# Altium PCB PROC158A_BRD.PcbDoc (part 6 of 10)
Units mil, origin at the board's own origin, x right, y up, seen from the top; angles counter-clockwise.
Board outline 3346.45 x 4921.26 mil, 8 copper layers (Top Layer, GND1, SIG1, PWR1, PWR2, SIG2, GND2, Bottom Layer), stack 54.534 mil thick; 718 components, 459 nets, 2307 pads, 1179 vias.
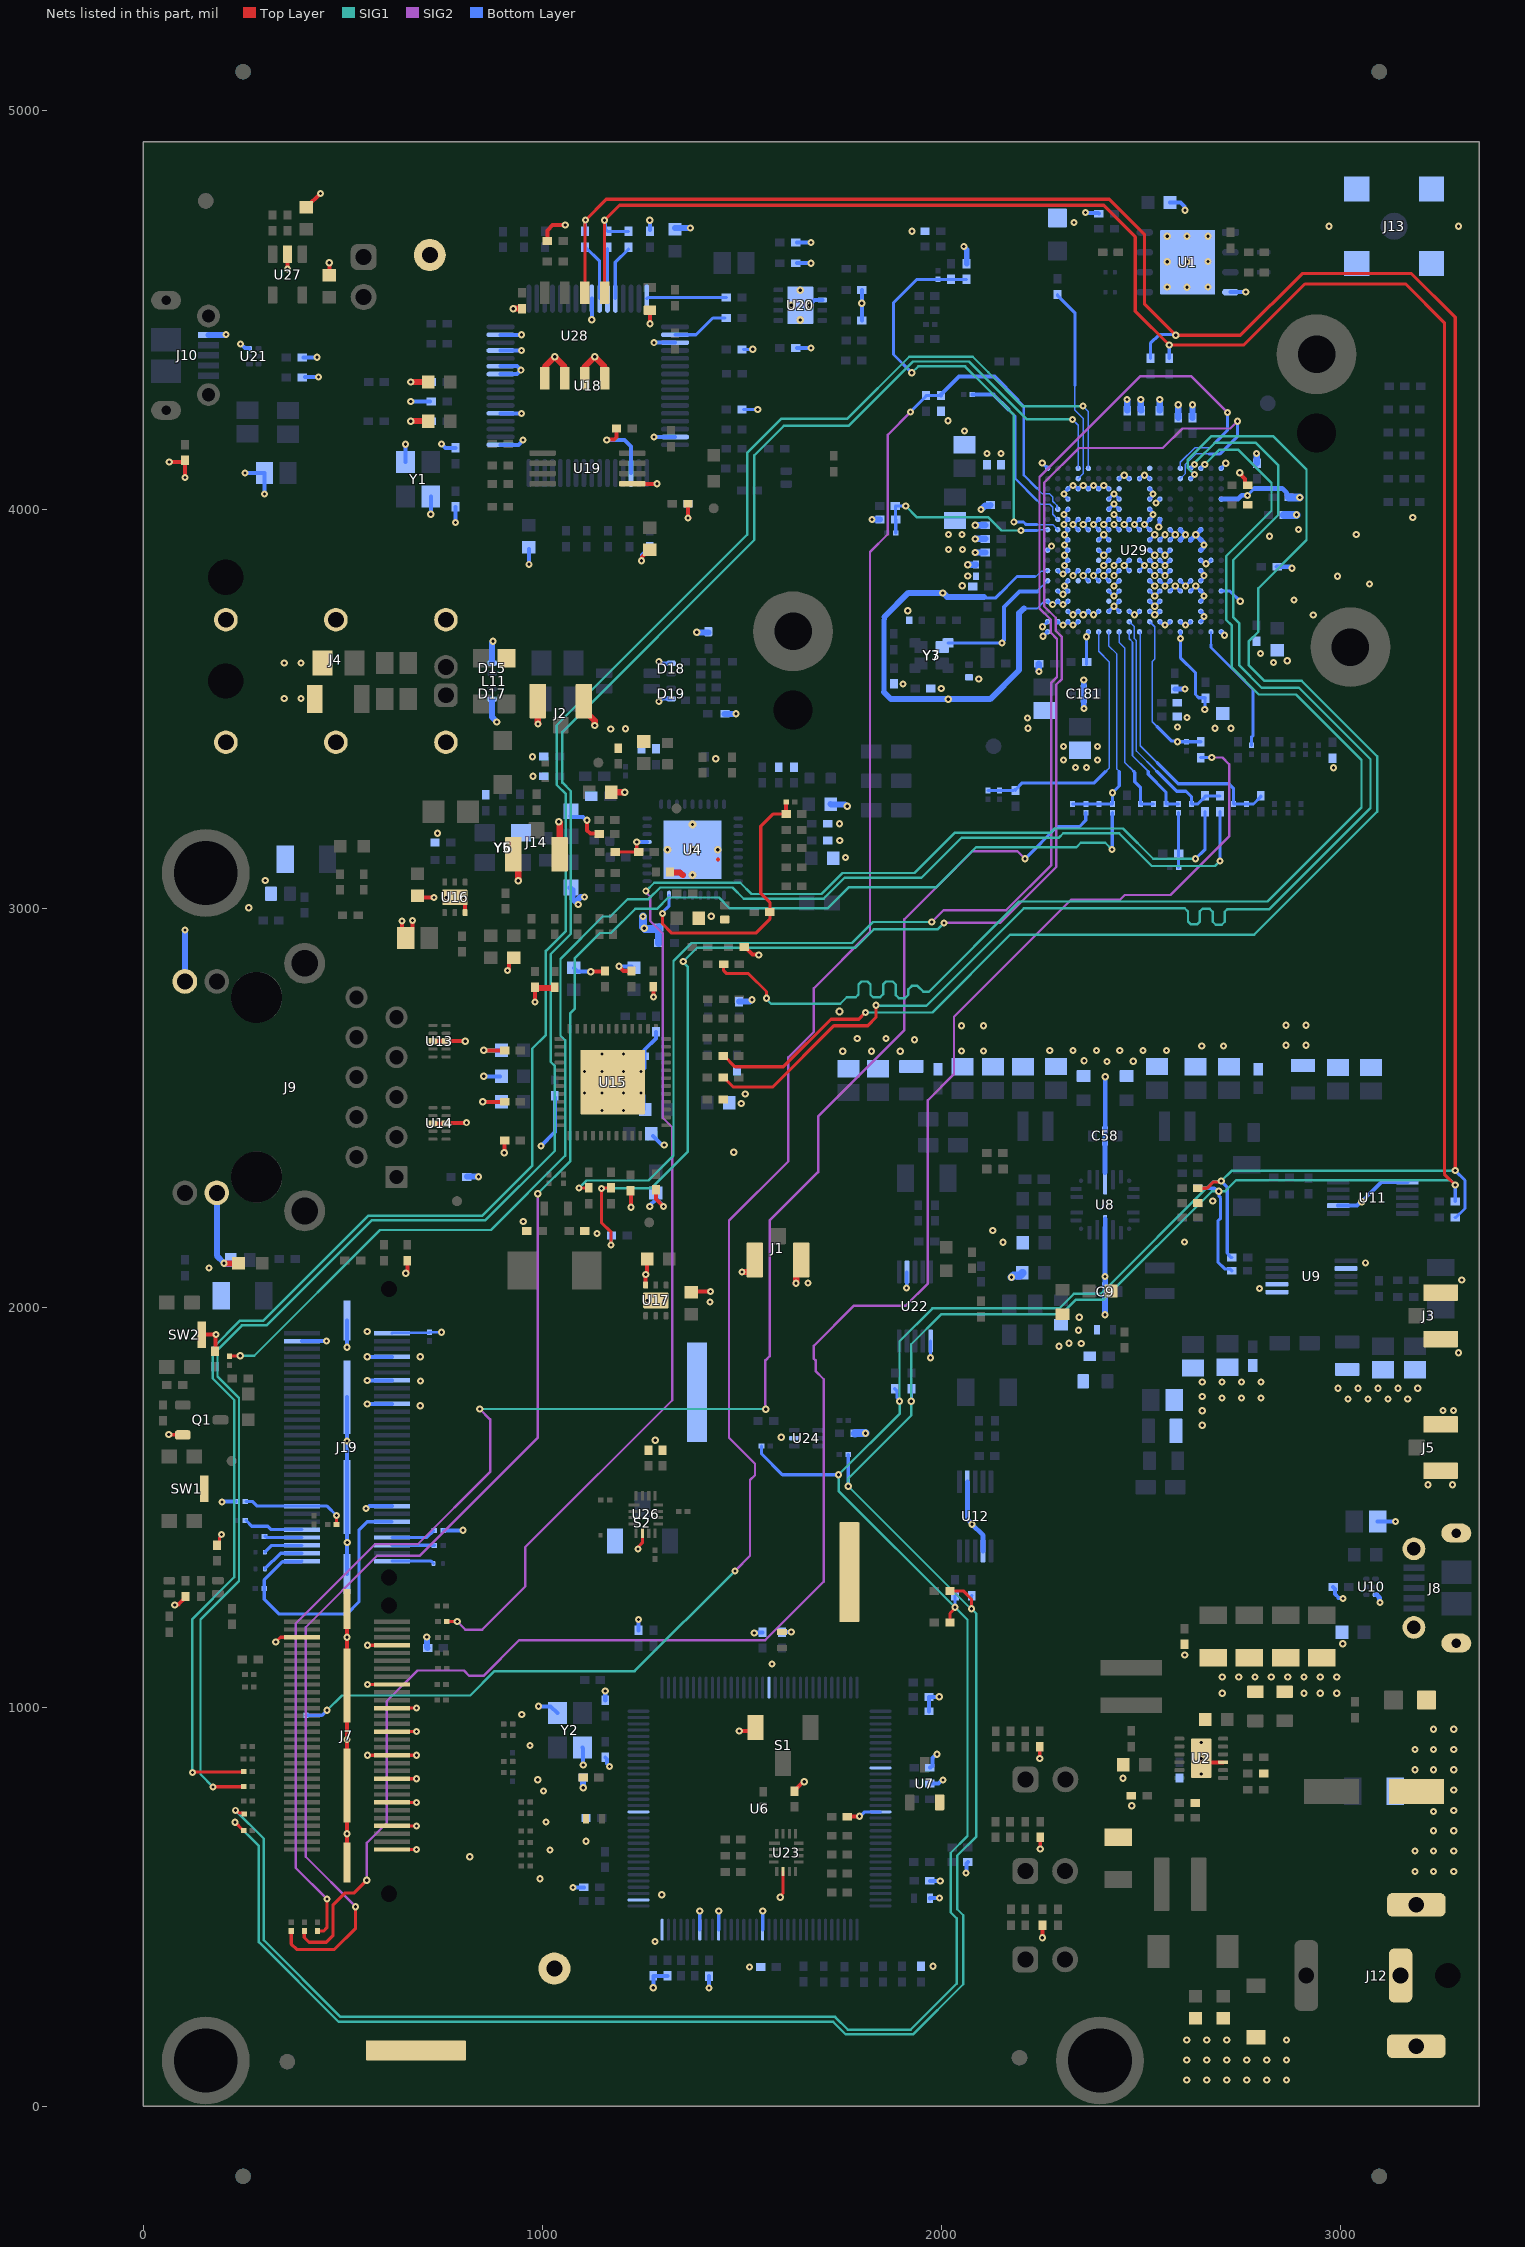
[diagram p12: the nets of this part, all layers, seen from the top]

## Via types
v1: diameter 18, hole 8, Top Layer to Bottom Layer, tented both sides, 1112 vias
v2: diameter 19.68, hole 7.87, Top Layer to Bottom Layer, 28 vias
v3: diameter 20, hole 10, Top Layer to Bottom Layer, tented both sides, 26 vias
v4: diameter 16/18/18/18/18/18/18/16 (per signal layer), hole 8, Top Layer to Bottom Layer, tented both sides, 13 vias

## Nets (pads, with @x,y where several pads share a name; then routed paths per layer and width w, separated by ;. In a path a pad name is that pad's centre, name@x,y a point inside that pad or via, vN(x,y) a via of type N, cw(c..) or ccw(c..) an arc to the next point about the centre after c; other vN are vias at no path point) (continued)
GND: C1.1 C2.1 C4.2 C5.1 C6.1 C7.2 C8.1 C9.2 C10.2 C11.1 C12.1 C13.1 C15.2 C16.2 C18.1 C20.2 C22.1 C23.2 C24.1 C25.2 C26.2 C27.1 C28.1 C29.2 C30.2 C31.2 C32.1 C33.2 C35.1 C36.1 C37.2 C38.2 C39.2 C40.2 C41.2 C42.1 C43.1 C44.2 C45.2 C46.1 C47.1 C48.2 C49.2 C50.2 C51.1 C52.2 C53.2 C54.1 C55.1 C56.2 C57.2 C58.2 C59.2 C60.2 C61.2 C62.2 C63.1 C64.1 C65.2 C66.1 C67.1 C68.2 C69.1 C70.2 C71.1 C72.2 C73.1 C74.1 C75.1 C76.1 C77.2 C78.2 C79.2 C80.1 C82.2 C83.2 C84.2 C85.2 C86.2 C87.2 C88.2 C89.2 C90.2 C91.2 C92.1 C93.2 C94.2 C95.2 C96.1 C97.2 C98.1 C99.2 C100.2 C101.2 C102.2 C103.2 C104.2 C105.1 C106.2 C107.1 C108.2 C109.1 C110.2 C111.1 C112.2 C113.1 C114.2 C115.1 C116.2 C117.1 C118.1 C119.2 C120.2 C121.2 C122.2 C124.2 C125.2 C126.2 C127.2 C128.2 C129.2 C130.2 C131.1 C132.2 C133.2 C134.2 C135.1 C136.1 C137.1 C138.1 C139.1 C140.1 C141.1 C142.1 C143.2 C144.1 C145.2 C146.1 C147.1 C148.1 C149.1 C150.1 C151.2 C152.2 C153.1 C154.2 C155.1 C158.2 C159.2 C160.2 C163.1 C164.1 C165.1 C166.2 C167.2 C168.1 C169.2 C170.1 C171.1 C172.1 C173.1 C174.1 C175.1 C176.1 C177.1 C178.1 C180.2 C181.2 C182.2 C183.2 C184.2 C185.2 C186.2 C187.2 C188.2 C189.2 C190.2 C191.2 C192.2 C193.2 C194.2 C195.2 C198.2 C199.2 C200.1 D1.2 D3.1 D6.2 D8.2 D10.1 D12.2 D14.1 D15.2 D17.2 D18.2 D19.2 J1.2 J1.3 J2.2 J2.3 J3.2 J3.3 J4.S1 J4.S2 J4.S3 J4.S4 J4.S5 J4.S6 J5.2 J5.3 J7.5 J7.8 J7.18 J7.24 J7.30 J7.36 J7.42 J7.48 J7.54 J7.60 J7.MP1 J7.MP2 J7.MP3 J7.MP4 J8.6 J8.9 J8.10 J8.11 J9.12 J9.13 J10.5 J12.2 J12.S1 J12.S2 J13.2 J14.2 J14.3 J19.16 J19.42 J19.48 J19.54 J19.57 J19.60 J19.MP1 J19.MP2 J19.MP3 J19.MP4 J21.1 J22.1 J23.1 L11.3 NT1.1 NT2.2 NT3.2 NT4.2 Q1.2 R1.2 R2.1 R8.2 R10.1 R17.1 R76.1 R86.1 R97.1 R102.2 R118.1 R119.2 R123.2 R126.2 R130.2 R137.1 R142.1 R143.1 R157.1 R172.1 R174.1 R175.1 R185.2 R194.1 R196.2 R203.2 R204.1 R208.1 R209.1 R251.2 R267.1 R282.1 R283.2 R285.1 R287.1 R288.1 R289.1 R294.1 R296.2 R302.1 R303.1 R307.1 R312.1 R313.1 R321.1 R326.1 R335.1 R337.2 R350.2 R400.2 R417.1 R512.2 S1.3 S2.3 SW1.5 SW2.5 TP7.1 TP9.1 U1.4 U1.9 U2.9 U2.13 U4.37 U6.10 U6.17 U6.48 U6.55 U6.58 U6.64 U6.66 U6.80 U6.114 U7.2 U8.10 U8.22 U9.1 U9.2 U9.7 U10.3 U11.1 U11.7 U12.2 U12.7 U13.3@725.63,2668.11 U13.8@758.51,2668.11 U14.3@725.63,2462.03 U14.8@758.51,2462.03 U15.49@1175.93,2565.54 U16.3 U16.7@780.58,3028.35 U17.3 U17.7@1283.94,2018.66 U18.1 U18.5 U18.10 U18.11 U18.13 U18.15 U18.25 U18.35 U18.47 U18.51 U19.5 U20.6 U20.9@1645.9,4511.81 U21.3 U22.1 U22.7 U23.6 U24.2 U26.6 U27.2 U28.1 U28.2 U28.3 U28.4 U29.A1 U29.A5 U29.A14 U29.A18 U29.B1 U29.B2 U29.B3 U29.B4 U29.B12 U29.B13 U29.B14 U29.B15 U29.B16 U29.C3 U29.C4 U29.C5 U29.C6 U29.C7 U29.C8 U29.C9 U29.C10 U29.C11 U29.C12 U29.C16 U29.D1 U29.D2 U29.D3 U29.D7 U29.D8 U29.D11 U29.D12 U29.D16 U29.E2 U29.E3 U29.E7 U29.E8 U29.E11 U29.E12 U29.E13 U29.E14 U29.E15 U29.E16 U29.E18 U29.F1 U29.F3 U29.F4 U29.F5 U29.F6 U29.F7 U29.F8 U29.F11 U29.F12 U29.F13 U29.F14 U29.F15 U29.F16 U29.G1 U29.G2 U29.G3 U29.G4 U29.G5 U29.G6 U29.G7 U29.G8 U29.G9 U29.G10 U29.G11 U29.G12 U29.G13 U29.G16 U29.H3 U29.H6 U29.H7 U29.H8 U29.H9 U29.H10 U29.H11 U29.H12 U29.H13 U29.H16 U29.H17 U29.J1 U29.J3 U29.J6 U29.J7 U29.J11 U29.J12 U29.J13 U29.J16 U29.K3 U29.K6 U29.K7 U29.K11 U29.K12 U29.K13 U29.K14 U29.K15 U29.K16 U29.L3 U29.L4 U29.L5 U29.L6 U29.L7 U29.L8 U29.L9 U29.L10 U29.L11 U29.L13 U29.L14 U29.L16 U29.M3 U29.M4 U29.M5 U29.M6 U29.M7 U29.M8 U29.M9 U29.M10 U29.M11 U29.M12 U29.N3 U29.N7 U29.N8 U29.N11 U29.P3 U29.P7 U29.P8 U29.P11 U29.P12 U29.P18 U29.R3 U29.R4 U29.R5 U29.R6 U29.R7 U29.R8 U29.R11 U29.T8 U29.T9 U29.T10 U29.T11 U29.U1 U29.U11 U29.U18 Y1.2 Y1.4 Y2.2 Y2.4 Y3.2 Y5.2 Y6.2 Y7.2 | length 15864.1
  Top Layer w7: v1(1595.75,523.58) 1595.75,526.56 1602.75,533.56 U23.6@1602.75,587.94
  Top Layer w8: R267.1@185.16,1405.66 191,1411.5 191,1423.93 196.31,1429.24 v1(196.31,1431.94) ; v1(332.09,1163.08) 343.68,1174.67 J7.5@397.49,1174.67 ; v1@561.77,879.4 v1@684.4,879.4 ; v1@561.77,1056.56 J7.18@623.08,1056.56 ; v1@561.77,1154.99 J7.8@623.08,1154.99 ; J7.60@623.08,643.18 v1@684.4,643.18 ; J7.54@623.08,702.23 v1@684.4,702.23 ; J7.48@623.08,761.29 v1@684.4,761.29 ; J7.42@623.08,820.34 v1@684.4,820.34 ; J7.30@623.08,938.45 v1@684.4,938.45 ; J7.24@623.08,997.51 v1@684.4,997.51 ; v1(1239,1395.81) 1240.91,1397.72 1240.91,1402.2 1250.43,1411.72 U26.6@1250.43,1435.19 ; v1(2245.64,871.29) R313.1@2245.64,900.17 ; v1(2246.93,644.67) R307.1@2246.93,673.54
  Top Layer w10: v1(63.77,1682.53) 64.12,1682.18 98.66,1682.18 Q1.2@99.01,1681.83 ; v1(64.94,4119.21) 104.25,4119.21 v1(104.25,4079.9) ; v1(79,1256) 80.53,1257.53 88.5,1257.53 105.96,1274.99 C105.1@105.96,1276.96 ; SW2.5@146.75,1932.78 147.11,1933.14 v1(181.92,1933.14) ; R335.1@179.39,1891.44 180.65,1892.71 180.65,1931.88 v1@181.56,1932.78 ; v1(361.36,4602.54) U27.2@361.36,4639.59 U27.2@361.36,4642.54 ; C145.2@408.44,4758.62 410.66,4758.62 443.86,4791.81 v1(444,4791.81) ; C149.1@466.12,4587.25 v1(466.12,4618.16) ; J7.MP4@510.29,611.09 v1(510.29,682.55) J7.MP3@510.29,803.61 v1(510.29,918.77) J7.MP2@510.29,1053.61 v1(510.29,1174.67) J7.MP1@510.29,1246.13 ; v1(648.13,2969.26) 648.13,2944.11 668.56,2944.11 674.11,2949.66 v1(674.11,2970.09) ; v1(657.5,2086.87) 661.43,2090.81 R118.1@661.43,2118.25 ; C48.2@687.02,3028.35 v1(728.16,3028.35) ; U14.3@725.63,2462.03 U14.8@758.51,2462.03 759.49,2463.02 809.02,2463.02 v1(810,2464) ; U13.3@725.63,2668.11 U13.8@758.51,2668.11 v1(806.42,2668.11) ; v2(802.23,3028.35) 806.17,3024.41 U16.3@806.17,2989.96 ; v1(850.52,2516.33) C188.2@901.41,2516.33 ; v1(853.06,2645.15) C189.2@901.41,2645.15 ; R337.2@901.41,2418.89 904.76,2415.54 904.76,2389.11 v1(904.17,2388.53) ; v1(912.62,2845.05) 912.62,2847.21 916.1,2850.69 916.1,2866.46 926.85,2877.21 R294.1@927.83,2877.21 ; v1(981.5,2766.54) R97.1@981.5,2799.29 ; R417.1@1012.52,4672.69 1012.52,4699.23 1025.72,4712.43 v1(1057.2,4712.43) ; R137.1@1034.65,2799.29 R97.1@981.5,2799.29 ; R137.1@1034.65,2803.23 R137.1@1030.65,2803.23 R97.1@981.5,2803.23 R97.1@981.5,2799.29 ; v1(1111.5,3221.35) 1111.5,3196.35 1119.83,3188.03 R350.2@1141.44,3188.03 ; v1(1121.01,2842.2) 1121.83,2843.02 1156.09,2843.02 C160.2@1156.91,2843.84 ; v1(1161,4173.81) 1162.33,4175.14 1179.6,4175.14 1185.46,4181 C86.2@1185.46,4202.72 ; v1(1191.71,2855.65) 1203.52,2843.84 C185.2@1223.16,2843.84 ; C184.2@1220.92,2289.53 1221.2,2289.24 1221.2,2252.57 v1(1221.49,2252.28) ; U19.5@1224.83,4064.47 v1(1286.74,4064.47) ; v1(1248,3871.7) 1249.53,3873.23 1249.53,3880.76 1267.78,3899.01 C90.2@1268.76,3899.01 ; U17.3@1258.35,2057.05 1258.35,2083.78 1262.45,2087.89 C65.2@1262.45,2122.43 ; v1(1269.17,4465.4) D1.2@1269.17,4499.01 ; R142.1@1277.72,2800.53 1277.86,2800.39 1277.86,2778.69 v1(1278,2778.55) ; C191.2@1284.2,2291.7 1284.2,2273.24 v1@1303.09,2254.35 ; C78.2@1364.68,4014.41 1364.68,3982.29 v1@1368.62,3978.36 ; C60.2@1375.46,2041.06 1375.52,2041.01 v1(1421.26,2041.01) ; 1439.2,3122.96 1439.29,3122.86 ; v1(1493,940) 1524.66,940 S1.3@1533.91,949.26 ; R289.1@1505.37,2903.81 1507.34,2903.81 1525.62,2885.53 1540.47,2885.53 v1(1542,2884) ; C98.1@1631.35,789.2 1631.35,791.17 1651.57,811.39 1654.14,811.39 v1(1655.67,812.92) ; R296.2@1763.89,725.22 1764.63,725.96 1793.14,725.96 v1(1793.88,726.69) ; v1(2252.26,422.29) R302.1@2252.26,453.72 ; v2(2650.36,871.52) 2660.2,861.68 U2.9@2705.09,861.68 ; v1(2747,4092) 2747,4089.84 2759.89,4076.94 2759.89,4065.71 2764.73,4060.87 C142.1@2766.68,4060.87
  Top Layer w15: v1(202.27,2111.76) 202.44,2111.59 238.32,2111.59 D8.2@238.49,2111.43 ; v1(669.98,4221.1) C68.2@713.89,4221.1 ; v1(669.98,4319.53) C72.2@713.89,4319.53 ; v1(926.85,4503.08) 926.92,4503.15 948.94,4503.15 C47.1@949.01,4503.22 ; U28.1@1005.83,4328.57 1005.83,4357.56 v1(1030.83,4382.56) 1055.83,4357.56 U28.2@1055.83,4328.57 ; U28.3@1105.83,4328.57 1105.83,4357.56 v1(1130.83,4382.56) 1155.83,4357.56 U28.4@1155.83,4328.57 ; D14.1@1319.63,3091.95 1320.73,3090.85 1344.05,3090.85 1350.33,3084.57 1351.6,3084.57
  Top Layer w16: J14.2@926.93,3136.24 938.93,3124.24 938.93,3070.38 v1(939.31,3070) ; J2.3@987.93,3520 988.62,3519.31 988.62,3463.38 v1(989,3463) ; v1(1040.71,3217.9) 1040.71,3217.36 1043.07,3215 J14.3@1043.07,3136.24 ; J2.2@1104.07,3520 1104.07,3497.36 1130.62,3470.82 1130.62,3459.38 v1(1131,3459) ; C11.1@1172.12,3292 1172.37,3291.75 1205.71,3291.75 v1(1205.96,3291.5) ; v1(1500,2090) 1519.26,2090 1531.93,2102.67 J1.3@1531.93,2119.96 ; v1(1634.87,2061.86) 1634.87,2062.4 1635.4,2062.93 1635.4,2107.29 J1.2@1648.07,2119.96
  SIG1 w15: v1@1101.89,797.92 v1(1102,797.81)
  Bottom Layer w4: 2233.14,3831.94 2236.12,3831.94 2249.95,3845.78 2262.2,3845.78 2263.48,3847.07 U29.G1@2265.3,3847.07
  Bottom Layer w4.5: 2205.73,3752.08 2239.08,3752.08 2256.17,3769.17 2264.18,3769.17 U29.D1@2265.3,3770.3 ; 2238.73,3794.9 U29.F1@2265.3,3821.48
  Bottom Layer w5.99: 2233.14,3831.94 2233.65,3832.45
  Bottom Layer w7: J19.60@623.08,1936.56 624.27,1937.74 715.68,1937.74 R196.2@716.86,1938.93 v1@746.98,1938.91 ; 2162.38,3805.39 2188.92,3831.94 2233.14,3831.94
  Bottom Layer w8: U6.58@1394.18,442.24 v1(1394.18,489) ; U6.55@1441.42,442.24 v1(1441.42,489) ; C89.2@1503.74,4250.39 v1(1539.43,4250.39) ; C82.2@1503.74,4400.69 1504.15,4401.1 1526.28,4401.1 v1(1526.7,4401.51) ; U6.48@1551.66,442.24 v1(1551.66,489) ; v1(1793.88,726.69) 1796.55,726.69 1807.37,737.52 U6.17@1846.93,737.52 ; v1(1912,2050) 1912.69,2050.69 1912.69,2089.48 U22.7@1913.37,2090.17 ; v1(1972.05,1875.19) 1972.24,1875.38 1972.24,1916.75 U22.1@1972.43,1916.94 ; Y7.2@2016.23,3665.7 2016.32,3665.6 2150.76,3665.6 v1(2150.86,3665.51) ; 2106.08,3781.19 2108.69,3778.58 2135.56,3778.58 2162.38,3805.39 ; v1(2252.19,4116.46) 2252.19,4116.27 2265.3,4103.16 U29.U1@2265.3,4102.97 ; v1(2252.51,3706.32) U29.B1@2265.3,3719.11 ; v1(2253.88,3682.61) 2254.13,3682.61 2265.05,3693.52 U29.A1@2265.3,3693.52 ; U29.D1@2265.3,3770.3 2273.73,3761.87 v1(2278.1,3761.87) 2282.47,3761.87 U29.D2@2290.89,3770.3 2299.32,3761.87 v1(2303.69,3761.87) 2308.06,3761.87 U29.D3@2316.48,3770.3 ; U29.J1@2265.3,3898.25 v4(2275.23,3908.17) ; U29.B2@2290.89,3719.11 2299.32,3710.69 v1(2303.69,3710.69) 2308.06,3710.69 U29.B3@2316.48,3719.11 2324.91,3710.69 v1(2329.28,3710.69) 2333.65,3710.69 U29.B4@2342.07,3719.11 ; U29.E2@2290.89,3795.89 2299.32,3787.46 v1(2303.69,3787.46) 2308.06,3787.46 U29.E3@2316.48,3795.89 2308.06,3804.31 v1(2308.06,3808.68) 2308.06,3813.05 U29.F3@2316.48,3821.48 ; U29.G2@2290.89,3847.07 2299.32,3838.64 v1(2303.69,3838.64) 2308.06,3838.64 U29.G3@2316.48,3847.07 2308.06,3855.49 v1(2308.06,3859.86) 2308.06,3864.23 U29.H3@2316.48,3872.66 2308.06,3881.08 v1(2308.06,3885.45) 2308.06,3889.82 U29.J3@2316.48,3898.25 2308.06,3906.67 v1(2308.06,3911.04) 2308.06,3915.41 U29.K3@2316.48,3923.84 2308.06,3932.26 v1(2308.06,3936.63) 2308.06,3941.01 U29.L3@2316.48,3949.43 2308.06,3957.85 2308.06,3966.6 U29.M3@2316.48,3975.02 2308.06,3983.44 2308.06,3992.19 U29.N3@2316.48,4000.61 ; U29.C3@2316.48,3744.71 2324.91,3736.28 v1(2329.28,3736.28) 2333.65,3736.28 U29.C4@2342.07,3744.71 2350.5,3736.28 v1(2354.87,3736.28) 2359.24,3736.28 U29.C5@2367.66,3744.71 2376.09,3736.28 v1(2380.46,3736.28) 2384.83,3736.28 U29.C6@2393.25,3744.71 ; U29.P3@2316.48,4026.2 2308.06,4034.63 2308.06,4043.37 U29.R3@2316.48,4051.79 2324.91,4060.22 v1(2329.28,4060.22) 2333.65,4060.22 U29.R4@2342.07,4051.79 2350.5,4060.22 v1(2354.87,4060.22) 2359.24,4060.22 U29.R5@2367.66,4051.79 2376.09,4060.22 v1(2380.46,4060.22) 2384.83,4060.22 U29.R6@2393.25,4051.79 2401.68,4060.22 v1(2406.05,4060.22) 2410.42,4060.22 U29.R7@2418.84,4051.79 ; v1(2329.28,3834.27) U29.G4@2342.07,3847.07 ; U29.L4@2342.07,3949.43 v1(2329.28,3962.23) U29.M4@2342.07,3975.02 ; C117.1@2363.11,3612 v1(2363.11,3681.22) ; v1@2363.11,3683.93 2366.57,3687.38 2366.57,3692.43 U29.A5@2367.66,3693.52 ; U29.F5@2367.66,3821.48 v1(2354.87,3834.27) U29.G5@2367.66,3847.07 ; U29.L5@2367.66,3949.43 v1(2354.87,3962.23) U29.M5@2367.66,3975.02 ; U29.F6@2393.25,3821.48 v1(2380.46,3834.27) U29.G6@2393.25,3847.07 ; U29.J6@2393.25,3898.25 v1(2406.05,3885.45) U29.J7@2418.84,3898.25 ; U29.K6@2393.25,3923.84 v1(2406.05,3936.64) U29.K7@2418.84,3923.84 ; U29.L6@2393.25,3949.43 v1(2380.46,3962.23) U29.M6@2393.25,3975.02 ; v1(2406.05,3859.86) U29.H7@2418.84,3872.66 ; U29.C7@2418.84,3744.71 v1(2431.64,3757.5) ; U29.E7@2418.84,3795.89 v1(2431.64,3783.09) U29.E8@2444.44,3795.89 ; U29.F7@2418.84,3821.48 v1(2406.05,3834.27) U29.G7@2418.84,3847.07 ; U29.L7@2418.84,3949.43 v1(2406.05,3962.23) U29.M7@2418.84,3975.02 ; U29.N7@2418.84,4000.61 v1(2431.64,4013.41) U29.N8@2444.44,4000.61 ; U29.P7@2418.84,4026.2 v1(2431.64,4039) U29.P8@2444.44,4026.2 ; v1(2431.64,3808.68) U29.F8@2444.44,3821.48 ; v1(2431.64,3834.27) U29.G8@2444.44,3847.07 ; v1(2431.64,3859.86) U29.H8@2444.44,3872.66 ; v1(2431.64,3962.23) U29.L8@2444.44,3949.43 ; v1(2431.64,3987.82) U29.M8@2444.44,3975.02 ; U29.C8@2444.44,3744.71 v1(2431.64,3757.5) ; U29.D8@2444.44,3770.3 v1(2431.64,3757.5) ; U29.T8@2444.44,4077.38 2452.86,4085.81 v1(2457.23,4085.81) 2461.6,4085.81 U29.T9@2470.03,4077.38 ; U29.C9@2470.03,3744.71 2478.45,3736.28 v1(2482.82,3736.28) 2487.19,3736.28 U29.C10@2495.62,3744.71 ; U29.G9@2470.03,3847.07 v1(2457.23,3859.86) U29.H9@2470.03,3872.66 ; U29.L9@2470.03,3949.43 v1(2457.23,3962.23) U29.M9@2470.03,3975.02 ; U29.G10@2495.62,3847.07 v1(2508.41,3859.86) U29.H10@2495.62,3872.66 ; U29.L10@2495.62,3949.43 v1(2482.82,3962.22) U29.M10@2495.62,3975.02 ; U29.T10@2495.62,4077.38 2504.04,4085.81 v1(2508.41,4085.81) 2512.78,4085.81 U29.T11@2521.21,4077.38 ; U29.C11@2521.21,3744.71 2529.63,3736.28 v1(2534,3736.28) 2538.37,3736.28 U29.C12@2546.8,3744.71 ; U29.D11@2521.21,3770.3 v1(2534,3757.5) U29.D12@2546.8,3770.3 ; U29.E11@2521.21,3795.89 v1(2534,3783.09) U29.E12@2546.8,3795.89 ; U29.F11@2521.21,3821.48 v1(2534,3808.68) ; U29.G11@2521.21,3847.07 v1(2534,3834.27) ; U29.H11@2521.21,3872.66 v1(2534,3859.86) ; U29.J11@2521.21,3898.25 v1(2534,3885.45) ; U29.K11@2521.21,3923.84 v1(2534,3936.64) ; U29.L11@2521.21,3949.43 v1(2508.41,3962.22) U29.M11@2521.21,3975.02 2529.63,3983.44 v1(2529.63,3987.82) 2529.63,3992.19 U29.N11@2521.21,4000.61 ; U29.P11@2521.21,4026.2 2529.63,4034.63 v1(2529.63,4039) 2529.63,4043.37 U29.R11@2521.21,4051.79 ; v1(2536.87,4016.28) U29.P12@2546.8,4026.2 ; U29.B12@2546.8,3719.11 2555.22,3710.69 v1(2559.59,3710.69) 2563.96,3710.69 U29.B13@2572.39,3719.11 ; U29.F12@2546.8,3821.48 v1(2559.59,3808.68) U29.F13@2572.39,3821.48 ; U29.G12@2546.8,3847.07 v1(2559.59,3834.27) U29.G13@2572.39,3847.07 ; U29.H12@2546.8,3872.66 v1(2559.59,3859.86) U29.H13@2572.39,3872.66 ; U29.J12@2546.8,3898.25 v1(2559.59,3885.45) U29.J13@2572.39,3898.25 ; U29.K12@2546.8,3923.84 v1(2559.59,3936.64) ; U29.E13@2572.39,3795.89 v1(2585.18,3808.68) U29.E14@2597.98,3795.89 ; U29.K13@2572.39,3923.84 v1(2585.18,3936.63) U29.L13@2572.39,3949.43 ; U29.A14@2597.98,3693.52 v1(2597.98,3676.82) 2597.98,3629.02 2635.86,3591.14 2635.86,3536.57 2643.84,3528.59 2660.04,3528.59 C139.1@2661,3527.63 ; U29.B14@2597.98,3719.11 2606.4,3710.69 v1(2610.77,3710.69) 2615.14,3710.69 U29.B15@2623.57,3719.11 ; U29.F14@2597.98,3821.48 v1(2610.77,3808.68) U29.F15@2623.57,3821.48 ; U29.E15@2623.57,3795.89 v1(2636.36,3808.68) U29.E16@2649.16,3795.89 2657.58,3787.46 v1(2657.58,3783.09) 2657.58,3778.72 U29.D16@2649.16,3770.3 ; U29.B16@2649.16,3719.11 2657.58,3727.54 v1(2657.58,3731.91) 2657.58,3736.28 U29.C16@2649.16,3744.71 ; U29.F16@2649.16,3821.48 2657.58,3829.9 v1(2657.58,3834.27) 2657.58,3838.64 U29.G16@2649.16,3847.07 ; U29.H16@2649.16,3872.66 2657.58,3864.23 v1(2661.95,3864.23) 2666.33,3864.23 U29.H17@2674.75,3872.66 ; v1(2659,3498.63) 2660,3499.63 C139.1@2660,3526.63 ; U29.A18@2700.34,3693.52 v1(2708.76,3685.1) ; U29.E18@2700.34,3795.89 2722.11,3795.89 v1(2748,3770) ; U29.U18@2700.34,4102.97 2700.34,4103.88 2711.51,4115.04 v1(2711.51,4115.95) ; v1@2767,4037 2767.5,4037 2783.68,4053.17
  Bottom Layer w10: v1(197,1514) 197.36,1514.36 231.34,1514.36 231.46,1514.47 R321.1@231.46,1514.71 ; v1(243.95,4414.8) 254.41,4404.34 264.1,4404.34 U21.3@265.01,4403.44 ; v1(255.13,4091.18) C39.2@303.71,4091.18 303.71,4038.7 v1(303.4,4039.01) ; v1(264.08,3002.19) v1@264.26,3002.19 ; J19.57@397.49,1916.88 v1@458.81,1916.88 ; R208.1@401.88,4381.16 v1(435.53,4381.16) ; C97.2@405.07,4331.74 v1(438.72,4331.74) ; J19.MP1@510.29,1333.61 510.53,1333.86 510.53,1411.64 v1(510.78,1411.88) 510.53,1412.13 510.53,1525.89 J19.MP2@510.29,1526.13 v1(510.29,1666.52) J19.MP3@510.29,1776.13 ; v1(510.29,1901.58) J19.MP4@510.29,1968.65 ; v1(558.11,1497.33) 560.28,1497.33 566.44,1503.49 J19.16@623.08,1503.49 ; v1@561.77,1759.4 J19.42@623.08,1759.4 ; v1@561.77,1818.45 J19.48@623.08,1818.45 ; v1@561.77,1877.51 J19.54@623.08,1877.51 ; Y1.2@657.29,4118.74 v1(657.29,4163.55) ; v1(669.98,4221.1) C69.1@717.82,4221.1 ; v1(669.98,4270.79) R157.1@717.82,4270.79 ; v1(669.98,4319.53) C73.1@717.82,4319.53 ; v1(720.28,3987.99) Y1.4@720.28,4032.13 ; v1(747.04,4164) 756.86,4154.18 C83.2@782.36,4154.18 ; R512.2@753.28,1441.96 753.28,1442.35 753.4,1442.47 800.24,1442.47 v1(800.78,1443.01) ; v1(782.36,3967.39) C84.2@782.36,4006.54 ; R400.2@810.21,2327.93 R400.2@810.78,2328.51 ; v1(850.52,2516.33) C59.2@890.99,2516.33 ; v1(853.06,2580.19) C56.2@893.54,2580.19 ; v1(853.06,2645.15) C187.2@893.54,2645.15 ; U18.1@895.17,4162.05 939.67,4162.05 v1(951.35,4173.72) ; U18.5@895.17,4240.79 v1(947.85,4240.79) ; U18.10@895.17,4339.21 936.51,4339.21 v1(946.35,4349.06) 936.51,4358.9 U18.11@895.17,4358.9 ; U18.13@895.17,4398.27 v1(947.85,4398.27) ; U18.15@895.17,4437.64 v1(947.85,4437.64) ; v1(965.97,3862.6) C79.2@965.97,3900.98 ; v1(990,1002) 1020.14,1002 Y2.2@1037.27,984.86 ; v1(996.01,2405.89) 1030.83,2440.71 C57.2@1030.83,2527.47 ; C121.2@1070,3232.5 1072.87,3229.62 1101.07,3229.62 1109.34,3221.35 v1(1111.5,3221.35) ; v1(1076.4,548) 1076.67,548.27 1103.57,548.27 C49.2@1103.84,548.54 ; C159.2@1078.54,2851.59 1087.92,2842.2 v1(1121.01,2842.2) ; Y2.4@1100.27,898.25 1102,896.51 v1(1102,855) ; v1@1123.52,4477.01 U18.25@1123.52,4528.19 ; C70.2@1157.31,873.87 1162.15,869.03 1162.15,859.02 1168,853.16 v1(1168,851) ; v1(1161,4173.81) 1206.09,4173.81 1221.94,4157.96 U18.51@1221.94,4091.18 ; v1(1191.71,2855.65) C53.2@1223.16,2855.65 ; C71.1@1240.63,1192.2 v1(1240.63,1219) ; v2(1246.79,2538.57) 1253.52,2531.85 C192.2@1253.52,2497.07 ; v2(1246.79,2592.51) 1255.64,2601.35 C193.2@1255.64,2630.46 1255.64,2646.63 1284.09,2675.09 R143.1@1284.09,2691.56 ; v1(1248,3871.7) 1249.53,3873.23 1249.53,3885.68 1268.76,3904.91 C91.2@1268.76,3906.88 ; v1(1268.73,2254.15) 1268.73,2256.32 1284.2,2271.79 C190.2@1284.2,2273.62 ; v1(1269,4724.81) 1269.09,4724.72 1269.09,4700.72 C88.2@1269.17,4700.64 ; C183.2@1276.86,2431.15 1298.78,2409.23 1303.77,2409.23 v1(1305.3,2407.7) ; v1(1277.59,297) R123.2@1277.59,326.49 R126.2@1313.19,326.49 ; v1(1279.5,4181.73) U18.47@1332.18,4181.73 ; v1(1279.5,4417.95) U18.35@1332.18,4417.95 ; C190.2@1284.2,2283.82 C190.2@1284.2,2273.62 ; v1(1291.57,3519.39) 1293.73,3519.39 1300.54,3526.19 D19.2@1322.29,3526.19 ; v1@1291.57,3621.14 1293.73,3621.14 1300.54,3614.34 D18.2@1322.29,3614.34 ; v1(1303.09,2253.97) 1303.09,2254.72 C190.2@1284.2,2273.62 ; v1(1364.68,3978.36) C77.2@1364.68,4014.41 ; v1(1417.54,296.41) R194.1@1417.54,325.9 ; v1(1530.37,1185.81) 1531.12,1186.56 1550.91,1186.56 C43.1@1551.66,1187.3 ; C64.1@1600.44,1187.3 1600.71,1187.57 1623.04,1187.57 v1(1623.3,1187.84) ; C85.2@1638.02,4404.56 1672.85,4404.56 v1(1673.01,4404.72) ; C93.2@1638.02,4617.01 v1(1673.01,4617.01) ; C94.2@1638.02,4668.86 v1(1673.01,4668.86) ; v2(1668.53,4511.81) 1681.33,4524.6 U20.6@1701.01,4524.6 ; R204.1@1800.03,4473.42 v1(1800.03,4516.46) R203.2@1800.03,4550.19 ; R285.1@1968.32,989.49 C109.1@1968.32,1025.56 1968.39,1025.63 1994.13,1025.63 v1(1994.2,1025.7) ; C67.1@1970.26,808.77 1992.62,808.77 2001.02,817.16 v1(2003.19,817.16) ; C66.1@1970.26,848.1 1972.23,848.1 1977.08,852.95 1977.08,872.14 1986.93,882 v1(1988,882) ; C76.1@1970.63,564.81 1970.73,564.71 1996.39,564.71 v1(1996.5,564.6) ; C41.2@1971,520.81 1971.34,521.16 1994.66,521.16 v1(1995,521.5) ; v1(2061,584.5) 2062.53,586.03 2062.53,608.23 R303.1@2065.84,611.54 ; v1(2150.86,3665.51) 2150.86,3667.67 2156.66,3673.48 2156.66,3755.48 2195.53,3794.35 2238.17,3794.35 2238.73,3794.9 ; v1(2360.08,4744.13) 2361.61,4742.6 2392.03,4742.6 C2.1@2393.63,4741 ; v1(2544,3956.22) 2544,3958.39 2546.09,3960.47 2546.09,3974.31 U29.M12@2546.8,3975.02 ; C1.1@2572.12,4769 2598.47,4769 2608.21,4759.26 2608.21,4751.2 v1(2609.74,4749.67) ; U1.4@2723.49,4544.33 2723.72,4544.57 2761.47,4544.57 v1(2761.7,4544.8) ; R174.1@2980.81,1301 2985.63,1296.18 2985.63,1282.95 2994.76,1273.82 3003.67,1273.82 v1(3005.2,1272.29) ; U11.7@2993.39,2256.23 3040.46,2256.23 3050.24,2266 v1(3052.4,2266) 3101.68,2315.28 U11.1@3166.61,2315.28 ; C45.2@3092.45,1465.35 3093.21,1464.59 v1(3136.85,1464.59)
  Bottom Layer w11: U8.10@2409.48,2202.21 U8.10@2409.48,2223.31
  Bottom Layer w12: v1(1157.1,1040.13) 1157.2,1040.03 1157.2,1017.15 C63.1@1157.31,1017.05 ; 1855.59,3542.5 1855.59,3698.37 1855.7,3698.48 1855.7,3724.07 1856.87,3725.23 1856.87,3731.07 ; U12.7@2064.41,1564.42 2064.41,1471.21 2076,1459.62 v1(2076,1458) 2103.69,1430.31 2103.69,1391.29 U12.2@2103.78,1391.19 ; v1(2409.48,2078.44) U8.10@2409.48,2202.21 ; U8.22@2409.48,2338.93 C58.2@2409.48,2414.88 C58.2@2409.48,2446.38 2409.71,2446.6 2409.71,2578.61 v1(2409.93,2578.84) ; C164.1@2584,3550.32 2584.32,3550 v1(2610,3550) ; U29.K14@2597.98,3923.84 v1(2610.77,3936.63) U29.L14@2597.98,3949.43 ; U29.K15@2623.57,3923.84 v1(2636.36,3936.63) ; U29.J16@2649.16,3898.25 2657.58,3906.67 v1(2657.58,3911.04) 2657.58,3915.41 U29.K16@2649.16,3923.84 v1(2636.36,3936.63) ; U29.L16@2649.16,3949.43 v1(2636.36,3936.63) ; U29.P18@2700.34,4026.2 2742.27,4026.2 2751.54,4035.46 v1@2765.72,4035.46 ; 2783.89,4052.96 2853.42,4052.96 2864.42,4041.96 2864.42,4034.35 2866.38,4034.35 C174.1@2870.23,4030.51 ; C170.1@2840.23,3856.66 2872.72,3856.66 2876.38,3853 v1(2878,3853) ; U10.3@3087.63,1281.31 3089.41,1281.31 3096.87,1273.85 3096.87,1263.35 v1(3098.01,1262.2)
  Bottom Layer w14: C95.2@1070,3052.32 1075.37,3046.94 1075.37,3024.86 1083.06,3017.18 ; v1(2055.61,4659.08) 2055.61,4658 2063.1,4650.51 2063.1,4620.62 2062.61,4620.13 C136.1@2062.61,4615.81 ; v1(2356.07,3573.13) 2356.19,3573.01 2356.19,3554 C181.2@2356.32,3553.88 C181.2@2356.32,3522.38 v1(2356.32,3501.74) ; v1(2409,1983) 2409.24,1983.24 2409.24,2024.62 C9.2@2409.48,2024.86 C9.2@2409.48,2056.36 v1(2409.48,2078.44)
  Bottom Layer w15: J9.12@104.25,2817.7 v1(104.25,2946.96) ; J10.5@163.39,4437.39 205.95,4437.39 v1(207.01,4438.45) ; J9.13@184.18,2288.17 184.18,2130.66 202.27,2112.57 v1(202.27,2111.76) ; v1(710,1175.81) 710.57,1175.24 710.57,1149.55 R326.1@712.32,1147.81 ; R400.2@810.78,2328.51 v1(839.7,2328.51) ; D17.2@873.77,3525.15 873.77,3479.6 v1(885.57,3467.79) ; D15.2@873.77,3615.37 873.77,3666.76 876.29,3669.29 v1(876.29,3670.1) ; 1089.83,3023.95 1094.96,3029.08 1104.8,3029.08 v1(1105.37,3029.65) ; C75.1@1101.89,823.24 C75.1@1101.89,823.24 1101.95,797.87 v1(1102,797.81) ; C87.2@1332.18,4705.53 1332.43,4705.28 v1(1370.48,4705.28) ; v1(1386.65,3692.29) C155.1@1415.62,3692.29 ; C166.2@1455.55,3488.17 v1(1484.52,3488.17) ; R288.1@1492.8,2767.23 1519.6,2767.23 1524.19,2771.81 v1(1525,2771.81) ; C8.1@1722.12,3261.81 1722.52,3261.41 1758.01,3261.41 1762.88,3256.53 v1(1763.69,3256.53) ; 1855.59,3542.5 1873.28,3524.81 2121.34,3524.81 2193.91,3597.38 2193.91,3740.26 2205.73,3752.08 ; 1856.87,3731.07 1916.8,3791 v1(2003,3791) 2003.81,3791 2013.62,3781.19 2106.08,3781.19
  Bottom Layer w16: v1(1825.5,3975) 1825.59,3974.91 1845.44,3974.91 C135.1@1845.54,3974.81 ; v1(2065.42,3861.55) 2065.74,3861.87 2085.78,3861.87 2085.91,3862 C102.2@2085.91,3862.19 ; v1(2084,3892.34) C111.1@2109.58,3892.34 ; v1(2084,3926.41) C180.2@2109.58,3926.41 ; v1(2084,3960.48) C107.1@2109.58,3960.48 ; v1(2098.86,4000) 2099.41,4000 2108.7,4009.29 2120.59,4009.29 C115.1@2122.44,4011.14 ; v1(2243.52,3594.52) C168.1@2243.52,3613.51 ; v1(2464.69,4275.25) v1(2464.69,4275.25) 2464.78,4247.96 C140.1@2464.86,4247.88 ; v1(2498.85,4275.25) 2499.23,4274.87 2499.23,4248.66 C163.1@2500.01,4247.88 ; C176.1@2546.16,4247.88 v1(2546.16,4275.25) ; C92.1@2592.82,4229.88 v1@2592.82,4255.25 ; C141.1@2628.47,4229.88 v1@2628.47,4255.25 ; v1(2789,4140) 2789.38,4139.62 2789.38,4116.57 C165.1@2789.81,4116.14
  Bottom Layer w20: v1(1252,2980.81) 1252,2954 v1(1255,2951) 1257.19,2948.81 C37.2@1280.28,2948.81 ; C46.1@1291.34,2914.18 C37.2@1291.34,2952.76 ; C133.2@1783.42,1685.81 1783.58,1685.97 v1@1808.97,1685.97 ; v1(2175.04,2076.71) 2179.59,2081.27 2196.69,2081.27 2202.44,2087.02 C171.1@2202.44,2088 ; C150.1@2858.23,3986.51 2858.38,3986.66 2875.51,3986.66 2875.63,3986.79 v1(2888.87,3986.79) ; C174.1@2870.23,4030.51 2870.38,4030.35 2896.65,4030.35 v1(2897,4030)
  other v1: 2614.2,65.74 2664.2,65.74 2714.2,65.74 2764.2,65.74 2814.2,65.74 2864.2,65.74 2614.2,115.74 2664.2,115.74 2714.2,115.74 2764.2,115.74 2814.2,115.74 2864.2,115.74 2614.2,165.74 2664.2,165.74 2714.2,165.74 2864.2,165.74 1518.9,349.16 1978,350.56 1282.2,413.1 1299,530 994,570 3186,588.42 3231.99,588.42 3283.01,588.42 818.05,625 3186,639.29 3231.99,639.29 3283.01,639.29 1019,642 684.8,643.18 1109,664 3231.99,690.16 3283.01,690.16 684.8,702.23 1009,712 3231.99,738.42 3283.01,741.03 2476,752.81 684.8,761.29 1003,790 3283.01,791.9 988,818 684.8,820.34 2454,821.81 3186,842.77 3231.99,842.77 3283.01,842.77 561.37,879.4 684.8,879.4 3186,893.64 3231.99,893.64 3283.01,893.64 969,904 684.8,938.45 3231.99,944.51 3283.01,944.51 948,981 684.8,997.51 2703.14,1034.42 2907.73,1034.42 2948.65,1034.42 2989.57,1034.42 561.37,1056.56 2703.14,1075.33 2744.06,1075.33 2784.98,1075.33 2825.9,1075.33 2866.81,1075.33 2907.73,1075.33 2948.65,1075.33 2989.57,1075.33 1575,1107.81 2608.95,1130.53 561.37,1154.99 3004.74,1158.73 3218.08,1557 3280.08,1557 1282.73,1668.41 1598,1675.81 1809,1686 2653,1706 2653,1742.16 3255.86,1742.77 3282,1743 693.64,1754.94 561.27,1759.4 3017.86,1771.81 3067.86,1771.81 3117.86,1771.81 3167.86,1771.81 2702.04,1774.47 2751.09,1774.47 2800.13,1774.47 2653,1778.31 2992.86,1798.81 3042.86,1798.81 3092.86,1798.81 3142.86,1798.81 3192.86,1798.81 2653,1814.47 2702.04,1814.47 2751.09,1814.47 2800.13,1814.47 694.18,1816.96 561.27,1818.45 561.27,1877.51 693.93,1877.51 3295.05,1887.77 2294,1903.81 2318.9,1911.18 2349.72,1910.79 459.31,1916.88 746.99,1938.9 561.27,1940.82 2342.72,1944.08 2344.8,1976.3 1420,2015 2796.4,2048.9 1665,2062 3302.99,2070 1258.68,2083.95 165,2100 3062,2112.81 2154.06,2164.52 2608.6,2165.39 1137,2186 2128.1,2193.8 952,2216 2679,2268 1479,2390 1497.94,2511.62 1507.87,2535.43 2414,2617 2480,2618 2357,2619 1752.44,2642.87 1824.39,2642.87 1896.34,2642.87 2050,2643.41 2105.07,2643.41 2270.6,2645.1 2329.14,2645.1 2387.68,2645.1 2446.22,2645.1 2504.76,2645.1 2563.3,2645.1 2651.8,2656 2706,2656 2863,2657.81 2913,2657.81 1932.31,2671.87 1788.41,2674.96 1860.36,2674.96 2050,2706.81 2105.07,2706.81 2863,2707.81 2913,2707.81 1423,2981 1089.8,3010.43 305.37,3070.35 1759,3128 1744.75,3171.06 737,3189 1744.09,3212.6 976,3331.81 2982,3353 2335,3354 2363,3354 2304.9,3372.72 2390.1,3372.72 1434,3375.81 975,3380.81 2305,3406 2390.1,3406 1171.25,3449.81 1208.25,3450.81 2216,3452 2685,3452 2725,3452 2591,3455 2215.25,3477.57 2615,3479 2016.6,3524.5 352.96,3526.19 395.06,3526.19 1999,3551.94 1903,3562.95 2093,3575.76 352.96,3615.37 395.06,3615.37 2831,3617 1291.57,3619.41 2866,3621 2799,3639 2931,3736 1914.94,3746.53 2883,3773 2051.7,3809.16 3072,3813 2065.42,3833.02 2991.7,3833 2017.46,3899.66 2052,3900 2821,3933 2017.46,3937.35 2051.35,3937.35 3038.6,3937.7 2893.9,3949.9 2306.56,3962.22 3180,3980 2306.56,3987.82 2765.84,4035.34 2306.56,4039 2114,4140 2149,4140 2057,4197 2016.24,4222.19 2592.82,4262.25 2628.47,4262.25 1123.52,4475.51 2565.3,4557 2614.5,4556.7 2667.1,4557.6 2565.3,4620.8 2614.5,4620.65 2667.1,4621.1 2565.3,4684.6 2614.5,4684.6 2667.1,4684.6 1925.47,4696.95 2970.4,4709.5 3294.4,4709.5 2331.7,4719.2
  other v2: 2650.36,832.15 2650.36,910.89 1262.29,2018.66 1305.59,2018.66 1148.96,2494.68 1202.9,2494.68 1105.06,2538.57 1148.96,2538.57 1202.9,2538.57 1105.06,2592.51 1148.96,2592.51 1202.9,2592.51 1148.96,2636.41 1202.9,2636.41 758.93,3028.35 1376.2,3084.57 1313.21,3147.57 1376.2,3147.57 1439.2,3147.57 1376.2,3210.56 1645.89,4474.41 1623.26,4511.81 1645.89,4549.21
  other v3: 1743.6,2742.24
GPADC1: C136.2 R80.1 R316.1 U29.L2 | length 1100.7
  SIG1 w6: v1(1925.25,4342.43) 1941.45,4358.63 2058.65,4358.63 2106.08,4311.21 2180.87,4236.41 v1(2180.87,3968.67)
  Bottom Layer w4: 2238.73,3962.19 2239.05,3962.19 2278.13,3962.19 U29.L2@2290.89,3949.43
  Bottom Layer w8: v1(1925.25,4342.43) 1879.38,4388.3 1879.38,4518.07 1937.48,4576.17 1963.69,4576.17 1963.82,4576.31 1991.25,4576.31 R80.1@1991.38,4576.44 R316.1@2023.75,4576.44 C136.2@2062.61,4576.44 ; v1(2180.87,3968.67) 2205.1,3968.67 2211.58,3962.19 2238.73,3962.19
GPADC2: C135.2 R82.1 R315.1 U29.L1 | length 476
  SIG1 w6: v1(1910,4009) 1938.64,3980.36 2106.08,3980.36 2117.27,3980.36 2150.33,3947.3 v1(2199.1,3947.3)
  Bottom Layer w4.2: 2238.73,3947.3 2239.05,3947.3 2241.32,3947.3 2243.45,3949.43 U29.L1@2265.3,3949.43
  Bottom Layer w8: R82.1@1884.91,3940.97 C135.2@1884.91,3974.81 1884.51,3975.21 1884.51,4008.58 R315.1@1884.12,4008.97 v1(1910,4009) ; v1(2199.1,3947.3) 2238.73,3947.3
GPADC5: C131.2 R91.1 R133.1 U29.N2 | length 5020.9
  SIG1 w6: v1(460.37,991.86) 497.51,1029 819,1029 880,1090 1231,1090 v1(1482,1341)
  SIG2 w6: v1(1482,1341) 1520,1379 1520,1568.43 1532.49,1580.91 1532.49,1609.51 1467.18,1674.82 1467.18,2218.53 1616,2367.35 1616,2628.02 1679.47,2691.49 1679.47,2800.41 1820.5,2941.44 1820.5,3893.5 1865,3938 1865,4187 v1(1922,4244)
  Bottom Layer w4: 2239.05,4052.91 2252.93,4039.03 2270.52,4039.03 2278.13,4031.42 2278.13,4020.92 2289.03,4010.02 2289.03,4002.47 U29.N2@2290.89,4000.61
  Bottom Layer w6: 2190.57,4274.37 2205.71,4259.24 2205.71,4086.26 2239.05,4052.91
  Bottom Layer w8: R91.1@408.16,979.39 447.9,979.39 v1(460.37,991.86) ; v1(1922,4244) 1922,4244.89 1960.71,4283.59 R133.1@1960.71,4285.56 C131.2@1998.62,4285.56
  Bottom Layer w10: C131.2@1998.62,4285.56 1998.62,4287.53 2043.84,4332.76 2132.19,4332.76 2190.57,4274.37
GPADC6: R94.1 U29.M2 | length 445.3
  Bottom Layer w4: 2239.05,4022.52 2248.13,4013.44 2270.52,4013.44 2278.13,4005.83 2278.13,3987.78 U29.M2@2290.89,3975.02
  Bottom Layer w6: 2166.95,4250.35 2184.71,4232.59 2184.71,4076.87 2238.73,4022.85 2239.05,4022.52
  Bottom Layer w10: R94.1@2077,4288 2129.3,4288 2166.95,4250.35
GPIO_3/XREF_CLK1: R21.1 R24.1 R219.1 R221.2 U29.A7 | length 546.4
  Bottom Layer w4: U29.A7@2418.84,3693.52 2418.84,3658.16 2439.09,3637.91 2439.09,3349.93 2445.02,3344
  Bottom Layer w8: R221.2@2327.86,3262.27 R219.1@2361.24,3262.27 ; R219.1@2361.3,3262.27 2393.82,3262.27 R21.1@2393.89,3262.33 ; R21.1@2394.61,3262.27 R24.1@2427.99,3262.27 ; R24.1@2427.88,3264.47 v1@2427.88,3290.34 ; v1(2427.99,3290.34) 2445.02,3307.37 2445.02,3344
GPIO_4/XREF_CLK0: R25.1 R228.2 U29.A8 | length 485.3
  Bottom Layer w4: U29.A8@2444.44,3693.52 2444.44,3667.24 2458.67,3653 2458.67,3366.33 2481,3344
  Bottom Layer w8: 2481,3344 2483.84,3341.16 2483.84,3317.62 2498.5,3302.97 R228.2@2498.5,3262.27 R25.1@2530.2,3262.27
GPIO_8: R28.1 R233.1 R235.2 U29.B9 | length 615.6
  Bottom Layer w4: U29.B9@2470.03,3719.11 2482.86,3706.28 2482.86,3676.58 2487.98,3671.46 2487.98,3394.92 2538.9,3344
  Bottom Layer w8: 2538.9,3344 2588.71,3294.19 2612.01,3294.19 2626,3280.2 R235.2@2626,3262.27 2641.85,3262.27 2660,3280.42 R28.1@2660,3282.39 R233.1@2697,3282.39
GPIO_9: R19.1 R217.2 U29.B11 | length 400.9
  Bottom Layer w4: U29.B11@2521.21,3719.11 2533.97,3706.35 2533.97,3625.54 2527.88,3619.45 2527.88,3468.09 2540.06,3455.9
  Bottom Layer w8: 2540.06,3455.9 2576.04,3419.92 2589.24,3419.92 v1(2591.15,3418.01) R217.2@2613.94,3418.01 R19.1@2649.2,3418.01
GPIO_30: R23.2 R229.1 R231.2 U29.A10 | length 680.2
  Bottom Layer w4: U29.A10@2495.62,3693.52 2497.48,3691.66 2497.48,3686.57 2497.73,3686.32 2497.73,3408.22 2540.06,3365.89
  Bottom Layer w8: 2540.06,3365.89 2592.95,3313 2719,3313 2731.39,3300.61 R231.2@2731.39,3262.27 R229.1@2764.1,3262.27 2781.24,3262.27 2799.39,3280.42 R23.2@2799.39,3282.39
GPIO_31: R22.2 R224.1 R227.2 U29.A6 | length 678.7
  Bottom Layer w4: U29.A6@2393.25,3693.52 2393.25,3662.03 2393.25,3644.75 2419.43,3618.57 2419.43,3352.04 2411.39,3344
  Bottom Layer w8: R224.1@2116,3296 R227.2@2145,3296 2180,3296 R22.2@2182.5,3298.5 ; R22.2@2185,3296 2185,3297.97 2202.09,3315.06 2382.45,3315.06 2411.39,3344
HOSTIRQ_FTDI_IN: R151.1 U18.32 | length 200.3
  Bottom Layer w8: U18.32@1261.31,4528.19 1264.13,4531.01 R151.1@1460.43,4531.01
HOSTIRQ_FTDI_OUT: R153.1 U18.34 | length 141.8
  Bottom Layer w8: U18.34@1332.18,4437.64 1384.66,4437.64 1426.85,4479.83 R153.1@1456.49,4479.83
I2C_SCL_FTDI: R148.1 U18.26 | length 144.8
  Bottom Layer w8: R148.1@1106.89,4657.33 1107.87,4657.33 1143.2,4622 U18.26@1143.2,4528.19
I2C_SDA_FTDI_IN: R149.1 U18.27 | length 125.2
  Bottom Layer w8: U18.27@1162.89,4528.19 R149.1@1162.89,4653.39
I2C_SDA_FTDI_OUT: R150.1 U18.28 | length 138.2
  Bottom Layer w8: U18.28@1182.57,4528.19 1182.57,4619.43 R150.1@1215.81,4652.67
LED_0: R61.1 R77.2 R258.1 U4.35 | length 719.7
  Top Layer w8: v1(1300.78,2988.14) 1300.78,2962.04 1324,2938.81 1534.81,2938.81 1569.84,2973.84 1569.84,3015.72 1546.68,3038.89 1546.68,3206.49 1577.18,3236.99 R258.1@1610.38,3236.99
  Top Layer w10: R258.1@1610.38,3236.99 R61.1@1610.38,3266.81
  Bottom Layer w8: v1(1300.78,2988.14) 1300.78,2990.75 1317.15,3007.12 U4.35@1317.15,3033.39
LED_1: R13.1 R93.2 U4.6 | length 108.2
  Top Layer w8: R13.1@1182.57,3142.2 R93.2@1237.94,3142.2 ; v1(1236.03,3167.25) 1236.03,3147 R93.2@1240.65,3142.38
  Bottom Layer w10: v1(1236.03,3167.25) U4.6@1262.03,3167.25
MCU_CLK_OUT: R165.1 R216.1 U29.A9 | length 501
  Bottom Layer w4: U29.A9@2470.03,3693.52 2470.03,3675.98 2478.18,3667.83 2478.18,3662.03 2478.18,3383.28 2517.45,3344
  Bottom Layer w8: 2517.45,3344 2517.45,3336.72 2561.9,3292.27 R216.1@2561.9,3262.27 R165.1@2593.6,3262.27
MCU_CLKOUT: R5.2 R6.1 R165.2 | length 137.2
  Bottom Layer w8: R5.2@2593.6,3103 R6.1@2593.6,3138 R165.2@2593.6,3240.22
MIPI_DBG_DETECT: J19.15 R226.2 R321.2 | length 263.6
  Top Layer w8: R226.2@484,1457.42 v1@484,1479.65
  Bottom Layer w8: R321.2@257.44,1514.71 274.46,1514.71 285.68,1503.49 J19.15@397.49,1503.49 460.54,1503.49 484.04,1479.99 v1(484.04,1479.69)
MIPI_JTAG_NRST: J19.9 R508.2 | length 149.7
  Bottom Layer w8: R508.2@257.44,1467.61 271.9,1453.16 311.81,1453.16 320.52,1444.44 J19.9@397.49,1444.44
MIPI_NRST: J19.6 R243.1 | length 105.8
  Bottom Layer w8: J19.6@623.3,1405.28 R243.1@729.07,1405.28
MIPI_RTCK: J19.7 R244.2 | length 93.1
  Bottom Layer w8: R244.2@305.65,1427.81 308.71,1424.75 J19.7@397.49,1424.75
MIPI_TCK: J19.3 R375.1 | length 109.2
  Bottom Layer w8: R375.1@304.64,1346.03 343.99,1385.38 J19.3@397.49,1385.38
MIPI_TDI: J19.5 R376.1 | length 99.9
  Bottom Layer w8: R376.1@304.64,1388.1 321.61,1405.07 J19.5@397.49,1405.07
MIPI_TMS: J19.2 R374.2 | length 106.6
  Bottom Layer w8: J19.2@623.08,1365.7 721,1365.7 R374.2@727.13,1359.57
MIPI_TRSTPD: J19.8 R512.1 | length 111.3
  Bottom Layer w8: J19.8@623.08,1424.75 710.12,1424.75 R512.1@727.3,1441.93
MIPI_VREF_DEBUG: J19.1 J19.12 R503.2 | length 699.1
  Bottom Layer w8: J19.1@397.49,1365.7 396,1364.21 348.44,1364.21 302.91,1318.68 R503.2@302.91,1297.35 302.91,1269.88 339.35,1233.45 510.58,1233.45 540.27,1263.14 540.27,1443.12 561.27,1464.12 J19.12@623.08,1464.12
MSS_EPWMA0: R28.2 R81.1 | length 3796.4
  Top Layer w8: R81.1@760.24,1214.04 v1(786.39,1214.04)
  SIG1 w6: v1(1259,3044) 1280,3065 1495.52,3065 1523.7,3036.81 1699.25,3036.81 1751.87,3089.43 1931.93,3089.43 2032.49,3190 2271.65,3190 2282.65,3201 2454,3201 2530,3125 v1(2636,3125)
  SIG2 w6: v1(786.39,1214.04) 806.43,1194 849,1194 957,1302 957,1400.64 1325,1768.64 1325,2452.34 1301.2,2476.14 1301.2,2938.23 1270,2969.43 1270,3029.75 1259,3040.75 v1(1259,3044)
  Bottom Layer w8: v1(2636,3125) 2660,3149 R28.2@2660,3243.02
MSS_EPWMA1: R19.2 R198.1 | length 4767.1
  Top Layer w8: R198.1@403.34,438.98 403.34,422.73 415.07,411 458.64,411 475,427.36 475,503.61 505.87,534.47 528.47,534.47 v1@559.78,565.78
  SIG2 w6: v1(560,566) 560,659.81 610,709.81 610,995 610,1014.81 686.87,1091.68 803.07,1091.68 816.64,1078.11 852.26,1078.11 941.96,1167.81 1558.26,1167.81 1704.77,1314.32 1704.77,1821.24 1684.33,1841.67 1684.33,1868.43 1680.03,1872.74 1680.03,1905.23 1780.42,2005.61 1910.04,2005.61 1965.69,2061.26 1965.69,2520.16 2031,2585.48 2031,2729.25 2324.12,3022.37 2446.8,3022.37 2458.6,3034.18 2572.93,3034.18 2720,3181.25 2720,3362 2703.36,3378.64 v1(2676.84,3378.64)
  Bottom Layer w8: R19.2@2649.2,3378.64 v1(2676.84,3378.64)
MSS_EPWMB0: R24.2 R197.1 | length 4632.9
  Top Layer w8: R197.1@370.69,438.98 370.69,406.31 384,393 479,393 532,446 v1(532,500)
  SIG1 w6: v1(988,2286) 1070,2368 1070,2738.81 1081.22,2750.03 1081.22,2876.12 1144.16,2939.06 1172.06,2939.06 1232.38,2999.38 1286.56,2999.38 1315.22,3028.04 1442.16,3028.04 1469.39,3000.81 1714.16,3000.81 1766.78,3053.43 1985.56,3053.43 2086.13,3154 2337.56,3154 2348.56,3165 2410,3165 v1(2427,3148)
  SIG2 w6: v1(532,500) 406.93,625.07 406.93,1200.12 586.27,1379.46 693.12,1379.46 988,1674.35 v1(988,2286)
  Bottom Layer w8: v1(2427,3148) 2427.49,3148.49 2427.49,3239.73 R24.2@2427.99,3240.22
MSS_GPIO_0: R328.1 U29.U5 | length 5427.5
  Top Layer w8: v1(123.04,836.47) 124.25,837.67 248.34,837.67 R328.1@249.55,838.88
  SIG1 w6: v1(123.04,836.47) 123.04,1220.68 227.89,1325.53 227.89,1454.07 227.89,1769.14 174,1823.03 174,1899.77 242.22,1967.99 300.99,1967.99 564.04,2231.04 849.6,2231.04 974.04,2355.48 974.04,2649.05 1008.66,2683.67 1008.66,2894.21 1058.71,2944.26 1058.71,3287.29 1036,3310 1036,3460 1512.54,3936.54 1512.54,4141.51 1598.73,4227.7 1763.95,4227.7 1918.88,4382.63 2077.91,4382.63 2116.62,4343.93 2201.55,4259 v1(2354,4259)
  Bottom Layer w4: v1(2354,4259) 2367.57,4245.43 2367.57,4134.47 2367.57,4134.18 2367.57,4103.07 U29.U5@2367.66,4102.97
MSS_GPIO_1: R329.1 U29.U4 | length 5354.6
  Top Layer w8: v1(175,800) 175.33,800.33 249.22,800.33 R329.1@249.55,800.66
  SIG1 w6: v1(175,800) 143.49,831.51 143.49,1219.26 239.89,1315.66 239.89,1774.11 186,1828 186,1894.8 247.19,1955.99 308.84,1955.99 571.89,2219.04 856.47,2219.04 1031.01,2393.58 1031.01,2605.5 1020.66,2615.85 1020.66,2886.14 1071,2936.49 1071,3294.87 1050,3315.87 1050,3443 1530.54,3923.54 1530.54,4135.64 1604.29,4209.39 1766.76,4209.39 1928,4370.63 2068.83,4370.63 2106.08,4333.39 2213.77,4225.69 v1(2327.53,4225.69)
  Bottom Layer w4: v1(2327.53,4225.69) 2342.07,4211.14 2342.07,4134.47 2342.07,4134.18 U29.U4@2342.07,4102.97
MSS_GPIO_2: R347.2 U29.T4 | length 493.4
  Bottom Layer w4: 2333.84,4311 2333.84,4248.74 2354.87,4227.71 2354.87,4134.47 2354.87,4090.18 U29.T4@2342.07,4077.38
  Bottom Layer w8: R347.2@2290,4538.63 2290,4536.66 2333.84,4492.83 2333.84,4311
MSS_GPIO_3: R114.1 R219.2 | length 4315
  Top Layer w8: R114.1@436,438.98 451.98,438.98 460,447 v1(460,519)
  SIG1 w6: v1(843,1746.61) 1558.62,1746.61 v1(1559.23,1746)
  SIG2 w6: v1(460,519) 382,597 382,1209.26 580.68,1407.95 687.66,1407.95 868.98,1589.27 868.98,1720.63 v1(843,1746.61) ; v1(1559.23,1746) 1558.49,1746.74 1558.49,1868.49 1569,1879 1569,2218.52 1690.62,2340.14 1690.62,2479.76 1906.58,2695.73 1906.58,2973.58 2077,3144 2190,3144 v1(2209,3125)
  Bottom Layer w8: v1(2209,3125) 2290,3206 2346.2,3206 2361.24,3221.04 R219.2@2361.24,3240.22
MSS_GPIO_8: R233.2 R334.2 | length 3516.1
  Top Layer w8: R334.2@215.95,1878.47 216.71,1879.24 242.24,1879.24 v1(243,1880)
  SIG1 w6: v1(243,1880) 278.19,1880 593.23,2195.04 870.69,2195.04 1057,2381.35 1057,2669.94 1045.22,2681.72 1045.22,2874.36 1151.21,2980.35 1169.96,2980.35 1213.53,3023.92 1265.92,3023.92 1295,3053 1476.08,3053 1504.27,3024.81 1704.22,3024.81 1756.84,3077.43 1949.6,3077.43 2050.17,3178 2293.68,3178 2304.68,3189 2444.46,3189 2526.46,3107 2684.88,3107 v1(2697.66,3119.78)
  Bottom Layer w8: R233.2@2697,3243.02 2697.33,3242.68 2697.33,3120.12 v1(2697.66,3119.78)
MSS_GPIO_11: R236.2 U29.A17 | length 329.4
  Bottom Layer w4: 2674.75,3662.03 U29.A17@2674.75,3693.52
  Bottom Layer w8: 2674.75,3662.03 2674.75,3654.25 2780,3549 2780,3433.39 2776,3429.39 R236.2@2776,3409.35
MSS_I2CA_SCL: R3.1 R27.2 R33.2 R52.1 R57.2 R58.2 R148.2 R276.1 R318.1 R390.1 U28.6 | length 11419.3
  Top Layer w8: v1(230.98,741.29) 233.68,741.29 240.24,734.73 249.51,734.73 249.51,733.55 R390.1@250.63,732.43 ; U28.6@1105.83,4543.13 1106.84,4544.15 1106.84,4724 1159.98,4777.13 2419.77,4777.13 2508.46,4688.44 2508.46,4514.17 v1(2586.24,4436.39) 2748.39,4436.39 2903,4591 3177,4591 3286.4,4481.6 v1(3286.4,2343.96) ; R276.1@2021,1212 2021,1234.73 2033.57,1247.29 v1(2033.57,1250) ; R52.1@2642.1,2299.62 2664.9,2299.62 2680.92,2315.63 2698.67,2315.63 v1(2700.59,2317.55)
  SIG1 w6: v1(230.98,741.29) 301.77,670.49 301.77,416.09 494.05,223.81 1733.07,223.81 1764.88,192 1922.74,192 2038,307.26 2038,470.77 2022.98,485.8 2022.98,635.03 2064.74,676.79 2064.74,1218.82 v1(2033.57,1250) 1742,1541.57 v1(1742,1582) 1895.3,1735.3 1895.3,1765.36 v1(1894.49,1766.17) 1894.49,1916.49 1976.81,1998.81 2038.76,1998.81 2294.75,1998.81 2330.98,2035.04 2398.62,2035.04 2681.13,2317.55 v1(2700.59,2317.55) 2727,2343.96 v1(3286.4,2343.96)
  Bottom Layer w8: R148.2@1106.89,4696.7 1107.37,4697.19 1107.37,4724.53 v1(1107.86,4725.01) ; R318.1@1548.68,1653.97 1548.68,1634.32 1601,1582 v1(1742,1582) ; R57.2@1882.53,1797.44 1888.37,1791.6 1888.37,1775 1894.49,1768.88 v1(1894.49,1766.17) ; v1(2033.57,1250) R58.2@2033.57,1279.3 ; R3.1@2523,4378.37 2523,4416 2545,4438 2584.63,4438 v1(2586.24,4436.39) ; v1(2700.59,2317.55) 2715.69,2302.44 2715.69,2137.28 2719.34,2133.63 2719.34,2131.66 2725.18,2125.82 R27.2@2727.15,2125.82 ; R33.2@3286.37,2226.39 3288.34,2226.39 3311,2249.05 3311,2319.35 v1(3286.4,2343.96)
MSS_I2CA_SDA: R29.2 R31.1 R35.2 R53.1 R59.2 R62.2 R149.2 R150.2 R277.1 R319.2 R391.1 U28.5 | length 11133.6
  Top Layer w8: v1(230.14,711.53) 230.14,711.34 249.53,691.95 R391.1@249.53,690.95 ; U28.5@1155.83,4543.13 1155.62,4543.34 1155.62,4724.31 v1(1155.41,4724.51) 1193.03,4762.13 2406.06,4762.13 2485.2,4682.99 2485.2,4496.8 v1(2570,4412) 2757,4412 2910,4565 3162.5,4565 3259.5,4468 3259.5,2335.04 v1(3286.68,2307.86) ; R277.1@2021,1291 2054,1291 2074.72,1270.28 v1(2074.72,1246.12)
  SIG1 w6: v1(230.14,711.53) 289.77,651.9 289.77,411.12 489.08,211.81 1728.1,211.81 1759.91,180 1928.16,180 2053.99,305.83 2053.99,478.44 2039.08,493.34 2039.08,627.94 2087,675.86 2087,1233.84 v1(2074.72,1246.12) 2072.88,1246.12 v1(1766,1553) 1766,1572.37 1924,1730.37 v1(1924,1766) 1924,1909 1999.51,1984.51 2300.67,1984.51 2336.89,2020.72 2405.32,2020.72 2676.44,2291.84 v1@2693.84,2291.84 ; v1(2694,2292) 2710.17,2292 2738.17,2320 3274.54,2320 v1(3286.68,2307.86)
  Bottom Layer w8: v1(1155.41,4724.51) 1157.33,4722.6 1157.33,4702.26 R149.2@1162.89,4696.7 R150.2@1215.81,4696.7 ; R319.2@1765.66,1632.28 1765.83,1632.11 1765.83,1553.17 v1(1766,1553) ; v1(1924,1766) 1924.27,1766.27 1924.27,1797.18 R62.2@1924.53,1797.44 ; v1(2074.72,1246.12) 2075.14,1246.55 2075.14,1278.88 R59.2@2075.57,1279.3 ; R31.1@2570,4378.37 v1(2570,4412) ; R53.1@2642.1,2299.62 2683.68,2299.62 2691.29,2292 v1(2694,2292) 2695.07,2290.93 2695.07,2279.37 2698.82,2275.62 2698.82,2224.41 2692,2217.59 2692,2114.84 2709.1,2097.75 2722.01,2097.75 R29.2@2726.87,2092.89 ; R35.2@3286.37,2266.39 3286.52,2266.54 3286.52,2307.71 v1(3286.68,2307.86)
MSS_MDIO_CLK: R249.1 R369.2 U29.U14 | length 3648.6
  Top Layer w8: v1(1091.71,2300) 1091.95,2300.24 1115.79,2300.24 R369.2@1116.04,2300.49
  SIG1 w6: v1(1091.71,2300) 1110.71,2319 1266,2319 1328.4,2381.4 1328.4,2868.66 1373.74,2914 1775.8,2914 1828.33,2966.54 v1(1975.38,2966.54)
  SIG2 w6: v1(1975.38,2966.54) 2004.85,2996 2161.47,2996 2274.9,3109.43 2274.9,3566.33 2289.1,3580.52 2289.1,3675.93 2273.69,3691.34 2273.69,3723.85 2245.23,3752.32 2245.23,4081.24 2497.99,4334 2624.64,4334 v1(2715.9,4242.75)
  Bottom Layer w4: U29.U14@2597.98,4102.97 2597.98,4118.47 2634.51,4155 2673,4155 2685.5,4167.5
  Bottom Layer w8: 2685.5,4167.5 2715.9,4197.9 v1(2715.9,4242.75)
MSS_MDIO_DATA: R247.1 R280.1 R413.2 U29.T14 | length 3741.7
  Top Layer w8: R247.1@1171.49,2300.49 1170.94,2299.93 1148.23,2299.93 v1(1147.67,2299.38) 1147.67,2213.95 1171.9,2189.72 v1(1171.9,2157.6)
  SIG1 w6: v1(1147.67,2299.38) 1272.31,2299.38 1364.4,2391.47 1364.4,2853.74 1352.8,2865.34 v1(1352.8,2867.6) 1387.2,2902 1784,2902 1830,2948 1990,2948 v1(2006,2964)
  SIG2 w6: v1(2006,2964) 2006.7,2964.7 2147.14,2964.7 2286.9,3104.46 2286.9,3561.36 2301.1,3575.55 2301.1,3680.9 2285.69,3696.31 2285.69,3728.83 2257.23,3757.29 2257.23,4067.25 2343.97,4154 2553.95,4154 2602.95,4203 2722.89,4203 v1(2740.96,4221.06)
  Bottom Layer w4: U29.T14@2597.98,4077.38 2610.74,4090.14 2610.74,4113.38 2636.53,4139.17 2670.39,4139.17
  Bottom Layer w8: v1(1171.9,2157.6) 1171.9,2180.57 R280.1@1173.03,2181.7 ; 2670.39,4139.17 2697.62,4139.17 2740.96,4182.51 v1(2740.96,4221.06)
MSS_RGMII_RCLK: R234.1 R290.1 U29.U15 | length 3440.3
  Top Layer w8: R290.1@1452.41,2577.02 1454.37,2577.02 1477.96,2553.43 1576.73,2553.43 1730.19,2706.9 1814.9,2706.9 1835.31,2727.31 v1(1835.31,2757.9)
  SIG1 w6: v1(1835.31,2757.9) 1836.2,2757.01 1962.01,2757.01 2206,3001 2609,3001 2617.04,2992.96 2617.04,2968.08 2624.52,2960.6 2639.52,2960.6 2647.04,2968.12 2647.04,2993.47 2653.57,3000 2671.2,3000 2679.24,2991.96 2679.24,2967.08 2686.72,2959.6 2701.72,2959.6 2709.24,2967.12 2709.24,2992.47 2715.77,2999 2821.04,2999 3074.2,3252.16 3074.2,3374.51 2895.06,3553.64 2801.44,3553.64 2745.76,3609.32 2745.76,3714.8 2730,3730.56 2730,3873.04 2843.71,3986.76 2843.71,4110.53 2787.29,4166.95 2684.23,4166.95 2638.56,4121.28 2638.56,4121.21 2633.49,4116.14 v4(2633.49,4112.9)
  Bottom Layer w8: U29.U15@2623.57,4102.97 v4(2633.49,4112.9)
MSS_RGMII_RCTL: R195.1 R245.1 U29.U16 | length 3296.6
  Top Layer w8: R195.1@1453.7,2860.81 1453.87,2860.64 1453.87,2844.82 1461.3,2837.39 1516.24,2837.39 1561.15,2792.48 v1(1561.15,2775.58)
  SIG1 w6: v1@1559.06,2775.59 1572.65,2762 1746.07,2762 1762.15,2778.08 1784.74,2778.08 1791.78,2785.12 1791.78,2810 1799.27,2817.48 1814.26,2817.48 1821.78,2809.96 1821.78,2784.6 1828.31,2778.08 1845.95,2778.08 1853.47,2785.6 1853.47,2810.48 1860.47,2817.48 1877.63,2817.48 1885.15,2809.96 1885.15,2783.38 1892.57,2775.96 1908.32,2775.96 1916.84,2784.48 1916.84,2798.07 1925.52,2806.74 1939.39,2806.74 1954.13,2792 1968,2792 2194,3018 2816,3018 3051.79,3253.79 3051.79,3372.88 2888.02,3536.64 2794.4,3536.64 2727,3604.04 2727,3709.52 2713,3723.52 2713,3883.46 2826.29,3996.75 2826.29,4066.32 2742.66,4149.95 2696.14,4149.95 v4(2659.08,4112.9)
  Bottom Layer w8: U29.U16@2649.16,4102.97 v4(2659.08,4112.9)
MSS_RGMII_RD0: R237.1 R325.1 U29.T15 | length 3435.2
  Top Layer w8: R325.1@1452.71,2631.31 1454.68,2631.31 1481.99,2604 1603.66,2604 1722.9,2723.24 1792.24,2723.24 v1(1809,2740)
  SIG1 w6: v1(1809,2740) 1977,2740 2172.05,2935.05 2782.96,2935.05 3091.2,3243.28 3091.2,3381.55 2902.11,3570.64 2808.48,3570.64 2769,3610.12 2769,3669.5 2793,3693.5 2793,3802.48 2914,3923.48 2914,4100.36 2830.41,4183.95 2675.99,4183.95 2616.29,4124.25 2616.29,4104.5 v4(2633.49,4087.31)
  Bottom Layer w8: U29.T15@2623.57,4077.38 v4(2633.49,4087.31)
